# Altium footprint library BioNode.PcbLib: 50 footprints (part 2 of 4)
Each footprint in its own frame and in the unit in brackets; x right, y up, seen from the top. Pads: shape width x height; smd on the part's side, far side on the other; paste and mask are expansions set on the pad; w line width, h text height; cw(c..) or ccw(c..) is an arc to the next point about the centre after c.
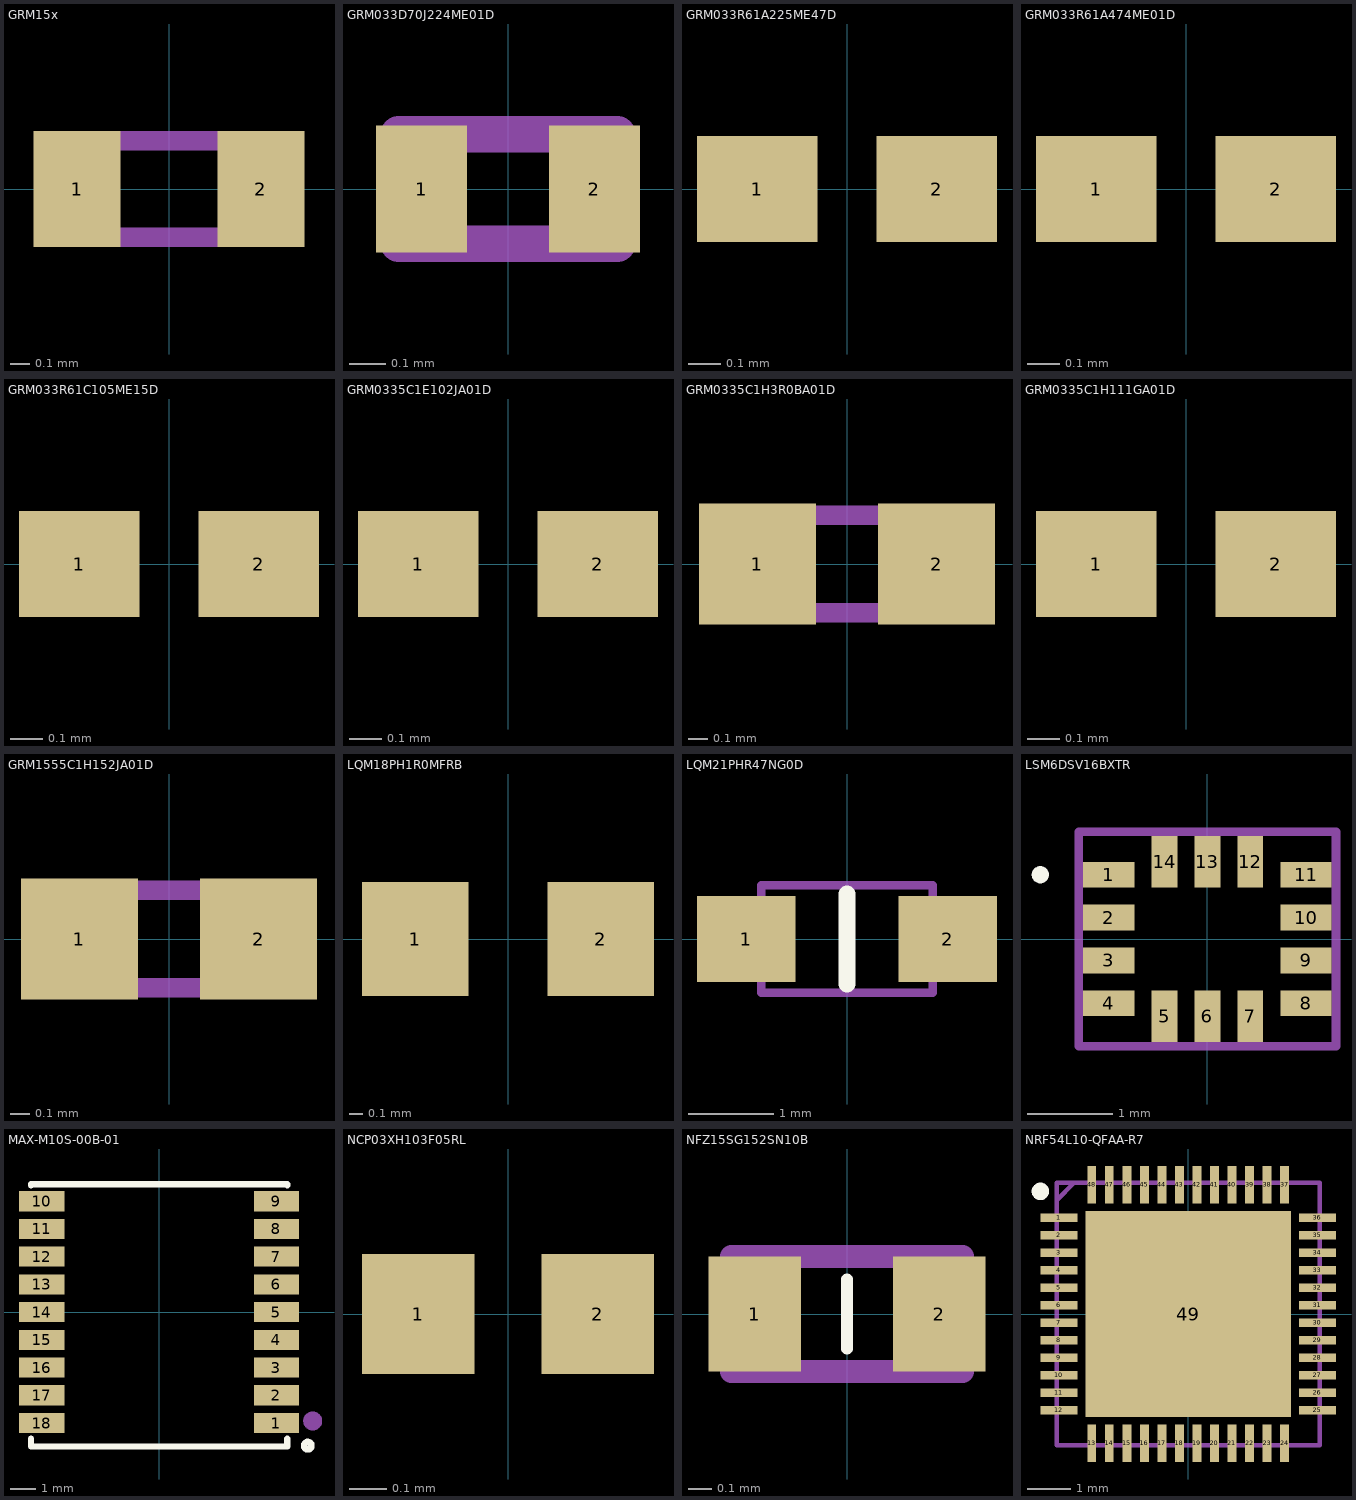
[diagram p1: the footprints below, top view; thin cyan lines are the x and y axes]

## GRM15x [mm]
pads (2):
  rect 0.45x0.6 smd: 1(-0.475,0) 2(0.475,0)
Mechanical 13:
  lines w0.1: -0.5,-0.25 0.5,-0.25 0.5,0.25 -0.5,0.25 -0.5,-0.25
3D body "GRM1555C1H472JE01D.stp": height 0.5, standoff 0, extent -0.5,-0.28 0.5,0.27

## GRM033D70J224ME01D [mm]
pads (2):
  rect 0.25x0.35 smd: 1(-0.237,0) 2(0.237,0)
Mechanical 13:
  lines w0.1: -0.3,-0.15 0.3,-0.15 0.3,0.15 -0.3,0.15 -0.3,-0.15
3D body "GRM033R61A225ME47D.stp": height 0.3, standoff 0, extent -0.3,-0.15 0.3,0.15

## GRM033R61A225ME47D [mm]
pads (2):
  rect 0.368x0.324 smd: 1(-0.274,0) 2(0.274,0)
3D body "GRM0335C1E102JA01D.stp": height 0.33, standoff 0, extent -0.3,-0.15 0.3,0.15

## GRM033R61A474ME01D [mm]
pads (2):
  rect 0.368x0.324 smd: 1(-0.274,0) 2(0.274,0)
3D body "CL03A104KO3NNNC.step": height 0.31, standoff 0, extent -0.3,-0.15 0.3,0.15

## GRM033R61C105ME15D [mm]
pads (2):
  rect 0.368x0.324 smd: 1(-0.274,0) 2(0.274,0)
3D body "CL03A104KO3NNNC.step": height 0.31, standoff 0, extent -0.3,-0.15 0.3,0.15

## GRM0335C1E102JA01D [mm]
pads (2):
  rect 0.368x0.324 smd: 1(-0.274,0) 2(0.274,0)
3D body "GRM0335C1E102JA01D.stp": height 0.33, standoff 0, extent -0.3,-0.15 0.3,0.15

## GRM0335C1H3R0BA01D [mm]
pads (2):
  rect 0.6x0.62 smd: 1(-0.46,0) 2(0.46,0)
Mechanical 13:
  lines w0.1: -0.5,-0.25 0.5,-0.25 0.5,0.25 -0.5,0.25 -0.5,-0.25
3D body "GRM1555C1H152JA01D.stp": height 0.5, standoff 0, extent -0.5,-0.25 0.5,0.25

## GRM0335C1H111GA01D [mm]
pads (2):
  rect 0.368x0.324 smd: 1(-0.274,0) 2(0.274,0)
3D body "CL03A104KO3NNNC.step": height 0.31, standoff 0, extent -0.3,-0.15 0.3,0.15

## GRM1555C1H152JA01D [mm]
pads (2):
  rect 0.6x0.62 smd: 1(-0.46,0) 2(0.46,0)
Mechanical 13:
  lines w0.1: -0.5,-0.25 0.5,-0.25 0.5,0.25 -0.5,0.25 -0.5,-0.25
3D body "GRM1555C1H152JA01D.stp": height 0.5, standoff 0, extent -0.5,-0.25 0.5,0.25

## LQM18PH1R0MFRB [mm]
pads (2):
  rect 0.8x0.864 smd: 1(-0.7,0) 2(0.7,0)
3D body "LQM18PN4R7MFRL.stp": height 0.95, standoff 0, extent -0.8,-0.4 0.8,0.4

## LQM21PHR47NG0D [mm]
pads (2):
  rect 1.15x1 smd: 1(-1.175,0) 2(1.175,0)
Top Overlay:
  lines w0.2: 0,-0.525 0,0.525
Mechanical 13:
  lines w0.1: -1,-0.625 1,-0.625 1,0.625 -1,0.625 -1,-0.625
3D body "LQM21PN4R7MGRD.stp": height 1, standoff 0, extent -1,-0.625 1,0.625

## LSM6DSV16BXTR [mm]
pads (14):
  rect 0.6x0.3 smd: 1(-1.15,0.75) 2(-1.15,0.25) 3(-1.15,-0.25) 4(-1.15,-0.75) 8(1.15,-0.75) 9(1.15,-0.25) 10(1.15,0.25) 11(1.15,0.75)
  rect 0.3x0.6 smd: 5(-0.5,-0.9) 6(0,-0.9) 7(0.5,-0.9) 12(0.5,0.9) 13(0,0.9) 14(-0.5,0.9)
Top Overlay:
  lines w0.1: -2,0.75 ccw(c-1.95,0.75) -1.9,0.75 ccw(c-1.95,0.75) -2,0.75
Mechanical 13:
  lines w0.1: -1.5,-1.25 -1.5,1.25 1.5,1.25 1.5,-1.25 -1.5,-1.25
3D body "LSM6DSV16XTR.stp": height 1.4, standoff 0, extent -1.549,-1.295 1.549,1.295

## MAX-M10S-00B-01 [mm]
pads (18):
  rect 1.8x0.8 smd: 1(4.658,-4.4) 2(4.658,-3.3) 3(4.658,-2.2) 4(4.658,-1.1) 5(4.658,0) 6(4.658,1.1) 7(4.658,2.2) 8(4.658,3.3) 9(4.658,4.4) 10(-4.658,4.4) 11(-4.658,3.3) 12(-4.658,2.2) 13(-4.658,1.1) 14(-4.658,0) 15(-4.658,-1.1) 16(-4.658,-2.2) 17(-4.658,-3.3) 18(-4.658,-4.4)
Top Overlay:
  circle w0.254: c5.9,-5.3 r0.15
  lines w0.254: -5.08,-5.031 -5.08,-5.334 5.08,-5.334 5.08,-5.031 ; -5.08,5.031 -5.08,5.08 5.08,5.08 5.08,5.031
Mechanical 6:
  region: 6.115,-4.074 6.198,-4.129 6.253,-4.212 6.273,-4.309 6.253,-4.407 6.198,-4.489 6.115,-4.545 6.018,-4.564 5.92,-4.545 5.838,-4.489 5.782,-4.407 5.763,-4.309 5.782,-4.212 5.838,-4.129 5.92,-4.074 6.018,-4.054
  lines w0.254: 6.346,-4.318 ccw(c6.096,-4.318) 6.346,-4.318
3D body "MAX-M10S-00B-01.step": height 2.51, standoff -0.01, extent -4.851,-5.05 4.851,5.05

## NCP03XH103F05RL [mm]
pads (2):
  rect 0.303x0.324 smd: 1(-0.242,0) 2(0.242,0)
3D body "NCP03XH103F05RL.stp": height 0.33, standoff 0, extent -0.3,-0.15 0.3,0.15

## NFZ15SG152SN10B [mm]
pads (2):
  rect 0.4x0.5 smd: 1(-0.4,0) 2(0.4,0)
Top Overlay:
  lines w0.05: 0,-0.15 0,0.15
Mechanical 13:
  lines w0.1: -0.5,-0.25 0.5,-0.25 0.5,0.25 -0.5,0.25 -0.5,-0.25
3D body "BLM15EG121SN1D.stp": height 0.5, standoff 0, extent -0.5,-0.25 0.5,0.25

## NRF54L10-QFAA-R7 [mm]
pads (49):
  rect 0.85x0.2 smd: 1(-2.95,2.2) 2(-2.95,1.8) 3(-2.95,1.4) 4(-2.95,1) 5(-2.95,0.6) 6(-2.95,0.2) 7(-2.95,-0.2) 8(-2.95,-0.6) 9(-2.95,-1) 10(-2.95,-1.4) 11(-2.95,-1.8) 12(-2.95,-2.2) 25(2.95,-2.2) 26(2.95,-1.8) 27(2.95,-1.4) 28(2.95,-1) 29(2.95,-0.6) 30(2.95,-0.2) 31(2.95,0.2) 32(2.95,0.6) 33(2.95,1) 34(2.95,1.4) 35(2.95,1.8) 36(2.95,2.2)
  rect 0.2x0.85 smd: 13(-2.2,-2.95) 14(-1.8,-2.95) 15(-1.4,-2.95) 16(-1,-2.95) 17(-0.6,-2.95) 18(-0.2,-2.95) 19(0.2,-2.95) 20(0.6,-2.95) 21(1,-2.95) 22(1.4,-2.95) 23(1.8,-2.95) 24(2.2,-2.95) 37(2.2,2.95) 38(1.8,2.95) 39(1.4,2.95) 40(1,2.95) 41(0.6,2.95) 42(0.2,2.95) 43(-0.2,2.95) 44(-0.6,2.95) 45(-1,2.95) 46(-1.4,2.95) 47(-1.8,2.95) 48(-2.2,2.95)
  rect 4.7x4.7 smd: 49(0,0)
Top Overlay:
  circle w0.2: c-3.375,2.8 r0.1
Mechanical 13:
  lines w0.1: -3,2.6 -2.6,3 ; -3,-3 -3,3 3,3 3,-3 -3,-3
3D body "NRF54L10-QFAA-R7.stp": height 0.9, standoff 0, extent -3.05,-3.05 3.05,3.05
